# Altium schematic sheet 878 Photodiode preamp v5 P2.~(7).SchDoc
size A4
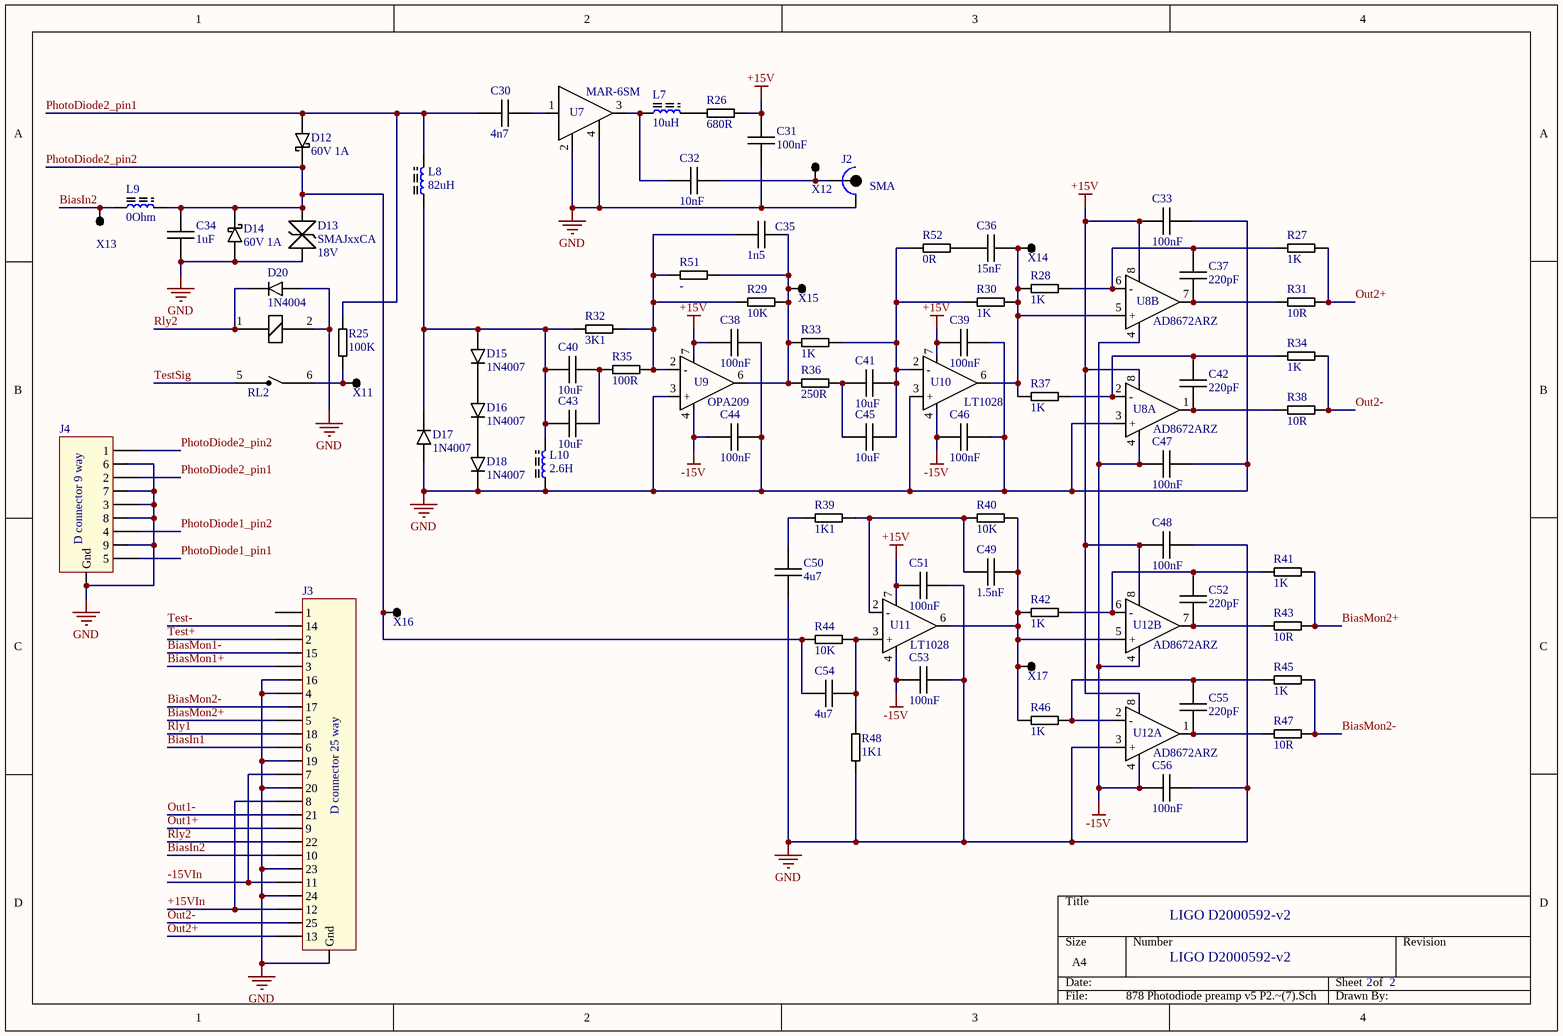
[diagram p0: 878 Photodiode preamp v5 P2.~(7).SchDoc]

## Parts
C30  value 4n7  [HS0805Long]  (hidden comment: Cap200)
C31  value 100nF  [HS0805Long]  (hidden comment: Cap200)
C32  value 10nF  [HS0805Long]  (hidden comment: Cap200)
C33  value 100nF  [HS0805Long]  (hidden comment: Cap200)
C34  value 1uF  [HS0805Long]  (hidden comment: Cap200)
C35  value 1n5  [HS0805Long]  (hidden comment: Cap200)
C36  value 15nF  [HS0805Long]  (hidden comment: Cap200)
C37  value 220pF  [HS0805Long]  (hidden comment: Cap200)
C38  value 100nF  [HS0805Long]  (hidden comment: Cap200)
C39  value 100nF  [HS0805Long]  (hidden comment: Cap200)
C40  value 10uF  [MKS2 7.2 11]  (hidden comment: Cap200)
C41  value 10uF  [MKS2 7.2 11]  (hidden comment: Cap200)
C42  value 220pF  [HS0805Long]  (hidden comment: Cap200)
C43  value 10uF  [MKS2 7.2 11]  (hidden comment: Cap200)
C44  value 100nF  [HS0805Long]  (hidden comment: Cap200)
C45  value 10uF  [MKS2 7.2 11]  (hidden comment: Cap200)
C46  value 100nF  [HS0805Long]  (hidden comment: Cap200)
C47  value 100nF  [HS0805Long]  (hidden comment: Cap200)
C48  value 100nF  [HS0805Long]  (hidden comment: Cap200)
C49  value 1.5nF  [HS0805Long]  (hidden comment: Cap200)
C50  value 4u7  [MKS2 7.2 8.5]  (hidden comment: Cap200)
C51  value 100nF  [HS0805Long]  (hidden comment: Cap200)
C52  value 220pF  [HS0805Long]  (hidden comment: Cap200)
C53  value 100nF  [HS0805Long]  (hidden comment: Cap200)
C54  value 4u7  [MKS2 7.2 8.5]  (hidden comment: Cap200)
C55  value 220pF  [HS0805Long]  (hidden comment: Cap200)
C56  value 100nF  [HS0805Long]  (hidden comment: Cap200)
D12  60V 1A  [SOD123]
D13  SMAJxxCA  [DO214AC]
D14  60V 1A  [SOD123]
D15  1N4007  [DO214AC]
D16  1N4007  [DO214AC]
D17  1N4007  [DO214AC]
D18  1N4007  [DO214AC]
D20  1N4004  [DO214AC]
J2  SMA  [PCB SMB]
J3  D connector 25 way  [D Socket Straight PCB 25 Way]
J4  D connector 9 way  [D Plug Straight PCB 9 Way]
L7  value 10uH  [HS1210]  (hidden comment: Inductor)
L8  value 82uH  [HS1210]  (hidden comment: Inductor)
L9  value 0Ohm  [HS1210]  (hidden comment: Inductor)
L10  value 2.6H  [2 way 0.1"]  (hidden comment: Inductor)
R25  value 100K  [hs0805long]  (hidden comment: Res)
R26  value 680R  [hs0805long]  (hidden comment: Res)
R27  value 1K  [hs0805long]  (hidden comment: Res)
R28  value 1K  [hs0805long]  (hidden comment: Res)
R29  value 10K  [SpecialR]  (hidden comment: Res)
R30  value 1K  [hs0805long]  (hidden comment: Res)
R31  value 10R  [hs0805long]  (hidden comment: Res)
R32  value 3K1  [hs0805long]  (hidden comment: Res)
R33  value 1K  [hs0805long]  (hidden comment: Res)
R34  value 1K  [hs0805long]  (hidden comment: Res)
R35  value 100R  [hs0805long]  (hidden comment: Res)
R36  value 250R  [hs0805long]  (hidden comment: Res)
R37  value 1K  [hs0805long]  (hidden comment: Res)
R38  value 10R  [hs0805long]  (hidden comment: Res)
R39  value 1K1  [hs0805long]  (hidden comment: Res)
R40  value 10K  [hs0805long]  (hidden comment: Res)
R41  value 1K  [hs0805long]  (hidden comment: Res)
R42  value 1K  [hs0805long]  (hidden comment: Res)
R43  value 10R  [hs0805long]  (hidden comment: Res)
R44  value 10K  [hs0805long]  (hidden comment: Res)
R45  value 1K  [hs0805long]  (hidden comment: Res)
R46  value 1K  [hs0805long]  (hidden comment: Res)
R47  value 10R  [hs0805long]  (hidden comment: Res)
R48  value 1K1  [hs0805long]  (hidden comment: Res)
R51  Res  [hs0805long]  (value not drawn)
R52  value 0R  [hs0805long]  (hidden comment: Res)
RL2  9901 relay  [9901 Relay]  (value not drawn)
U7  MAR-6SM  [ww107]
U8  AD8672ARZ  [SOIC 8]  (parts A,B of 2)
U9  OPA209  [SOIC 8]
U10  LT1028  [SOIC 8]
U11  LT1028  [SOIC 8]
U12  AD8672ARZ  [SOIC 8]  (parts A,B of 2)
X11  TestPoint  [SM Test point]  (value not drawn)
X12  TestPoint  [SM Test point]  (value not drawn)
X13  TestPoint  [SM Test point]  (value not drawn)
X14  TestPoint  [SM Test point]  (value not drawn)
X15  TestPoint  [SM Test point]  (value not drawn)
X16  TestPoint  [SM Test point]  (value not drawn)
X17  TestPoint  [SM Test point]  (value not drawn)

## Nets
+15V: C31.1 C33.1 C38.1 C39.1 C48.1 C51.1 R26.2 U8.8(V+) U9.7(V+) U10.7(V+) U11.7(V+) U12.8(V+)
-15V: C44.1 C46.1 C47.1 C53.1 C56.1 U8.4(V-) U9.4(V-) U10.4(V-) U11.4(V-) U12.4(V-)
GND: C31.2 C33.2 C34.2 C38.2 C39.2 C44.2 C46.2 C47.2 C48.2 C50.1 C51.2 C53.2 C56.2 D13.2 D14.A D17.A D18.K D20.A J2.2(Gnd) J3.4 J3.16 J3.19 J3.20 J3.23 J3.24 J3.26(Gnd) J4.3 J4.6 J4.7 J4.8 J4.9 J4.10(Gnd) L10.1 R48.1 RL2.2(Coil-) U7.2(gnd1) U7.4(GND2) U8.3(+) U9.3(+) U10.3(+) U12.3(+)
+15VIn: J3.8 J3.12
-15VIn: J3.7 J3.11
BiasIn1: J3.6
BiasIn2: J3.10 L9.1 X13.1
BiasMon1+: J3.3
BiasMon1-: J3.15
BiasMon2+: J3.5 R41.2 R43.2
BiasMon2-: J3.17 R45.2 R47.2
Out1+: J3.9
Out1-: J3.21
Out2+: J3.13 R27.2 R31.2
Out2-: J3.25 R34.2 R38.2
PhotoDiode1_pin1: J4.5
PhotoDiode1_pin2: J4.4
PhotoDiode2_pin1: C30.1 D12.A J4.2 L8.2 R25.2
PhotoDiode2_pin2: C34.1 C54.1 D12.K D13.1 D14.K J4.1 L9.2 R44.2 X16.1
Rly1: J3.18
Rly2: D20.K J3.22 RL2.1(Coil+)
Test+: J3.2
Test-: J3.14
TestSig: RL2.5(NO)
NetC30_2: C30.2 U7.1(IN)
NetC32_1: C32.1 L7.1 U7.3(OUT)
NetC32_2: C32.2 J2.1(Sig) X12.1
NetC35_1: C35.1 R29.1 R32.2 R35.2 R51.1 U9.2(-)
NetC35_2: C35.2 R29.2 R33.1 R36.1 R51.2 U9.6(OP) X15.1
NetC36_1: C36.1 R52.2
NetC36_2: C36.2 R28.1 R30.2 R37.1 U8.5(+) U10.6(OP) X14.1
NetC37_1: C37.1 R27.1 R28.2 U8.6(-)
NetC37_2: C37.2 R31.1 U8.7(OP)
NetC40_1: C40.1 C43.1 D15.A D17.K L8.1 L10.2 R32.1
NetC40_2: C40.2 C43.2 R35.1
NetC41_1: C41.1 C45.1 R36.2
NetC41_2: C41.2 C45.2 R30.1 R33.2 R52.1 U10.2(-)
NetC42_1: C42.1 R34.1 R37.2 U8.2(-)
NetC42_2: C42.2 R38.1 U8.1(OP)
NetC49_1: C49.1 R39.1 R40.1 U11.2(-)
NetC49_2: C49.2 R40.2 R42.1 R46.1 U11.6(OP) U12.5(+) X17.1
NetC50_2: C50.2 R39.2
NetC52_1: C52.1 R41.1 R42.2 U12.6(-)
NetC52_2: C52.2 R43.1 U12.7(OP)
NetC54_2: C54.2 R44.1 R48.2 U11.3(+)
NetC55_1: C55.1 R45.1 R46.2 U12.2(-)
NetC55_2: C55.2 R47.1 U12.1(OP)
NetD15_K: D15.K D16.A
NetD16_K: D16.K D18.A
NetL7_2: L7.2 R26.1
NetR25_1: R25.1 RL2.6(C) X11.1

Not connected (* = marked no-connect by the designer): J3 1

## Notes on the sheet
- LIGO D2000592-v2
- 2

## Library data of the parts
C30-C56 = Cap200: Cap 0.2" pitch
D12 D14 = Sckottky Diode: pin to pad: A>2 K>1
D13 = SMAJxxCA: TVS
D15-D18 D20 = 1N4004: pin to pad: A>2 K>1
J2 = PCB SMB
U8 U12 = DualOpAmp
U9-U11 = SingleOpAmp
